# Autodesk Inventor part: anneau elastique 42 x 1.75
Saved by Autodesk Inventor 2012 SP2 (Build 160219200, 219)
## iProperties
Created: 2013-04
Part Number: anneau elastique 42 x 1.75
Material: Default
Document SubType Name: Modeling
Designer: papa
Density: 1 g/cm^3
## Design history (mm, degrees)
node "anneau elastique 42 x 1.751"
node "anneau elastique 42 x 1.75"
node "Base1"
